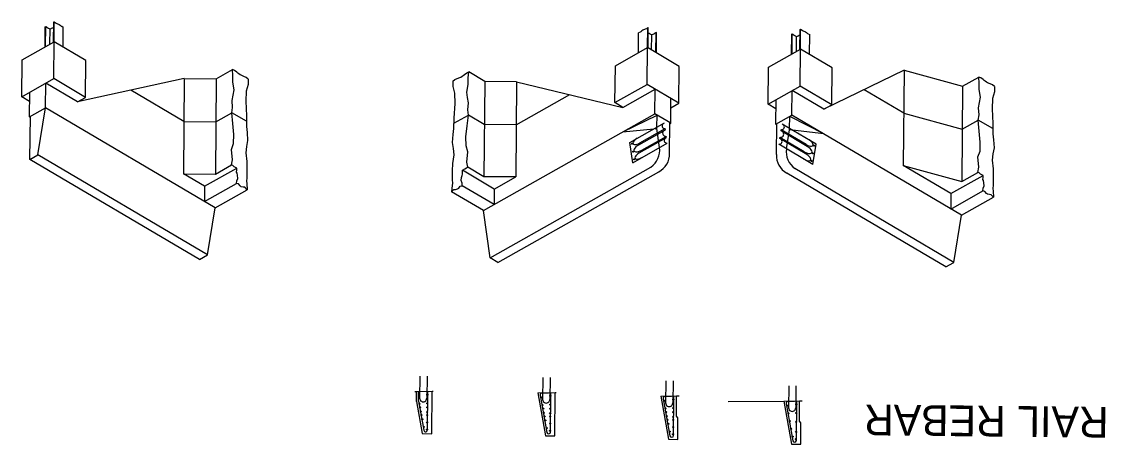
# Model space of a CAD drawing. Extents: x 631918 to 632319, y 373181 to 373282.
# Drawn here: x 631918.3 to 632006.4, y 373247.3 to 373281.7 of the extents above; entities that cross this region are included whole.
import ezdxf

# ---------------------------------------------------------------- set-up
doc = ezdxf.new("R2010")
doc.units = 0
for name, color, linetype in [('B_Boring', 7, 'Continuous'), ('BD-PROP-COSS', 7, 'Continuous'), ('BD-REMOVE', 7, 'Continuous'), ('R_Border_Scale', 7, 'Continuous'), ('R_Proposed Const Limits Cut', 7, 'Continuous'), ('R_Road Edge of Travel', 7, 'Continuous'), ('R_Shade Removal', 7, 'Continuous')]:
    doc.layers.add(name, color=color, linetype=linetype)

msp = doc.modelspace()

# ---------------------------------------------------------------- linework, layer by layer
at = {"layer": 'B_Boring'}
for p, q in [((631969.792, 373272.95), (631969.934, 373272.964)), ((631969.934, 373272.964), (631969.935, 373273.03)), ((631970.151, 373271.419), (631969.934, 373272.964)), ((631980.469, 373271.316), (631980.716, 373272.857)), ((631980.716, 373272.857), (631980.717, 373272.922)), ((631980.858, 373272.84), (631980.716, 373272.857))]:
    msp.add_line(p, q, dxfattribs=at)
at = {"layer": 'BD-PROP-COSS'}
for p, q in [((631950.664, 373252.836), (631950.646, 373251.044)), ((631951.247, 373252.83), (631951.229, 373251.038)), ((631960.663, 373252.736), (631960.645, 373250.945)), ((631961.247, 373252.73), (631961.229, 373250.939)), ((631970.661, 373252.454), (631970.643, 373250.663)), ((631971.244, 373252.449), (631971.226, 373250.657)), ((631980.657, 373252.052), (631980.64, 373250.261)), ((631981.241, 373252.047), (631981.223, 373250.255)), ((631950.56, 373250.791), (631950.568, 373251.599)), ((631951.287, 373248.474), (631951.318, 373251.591)), ((631960.452, 373251.286), (631960.996, 373248.267)), ((631961.121, 373251.452), (631960.597, 373251.457)), ((631961.286, 373248.292), (631961.318, 373251.492)), ((631971.119, 373251.171), (631970.595, 373251.176)), ((631971.283, 373248.01), (631971.315, 373251.21)), ((631950.56, 373250.791), (631950.982, 373248.447)), ((631970.45, 373251.004), (631970.994, 373247.985)), ((631980.447, 373250.602), (631980.991, 373247.583)), ((631981.115, 373250.768), (631980.592, 373250.774)), ((631981.28, 373247.608), (631981.312, 373250.808))]:
    msp.add_line(p, q, dxfattribs=at)
for centre in [(631950.606, 373251.211), (631951.274, 373251.329), (631960.528, 373251.112), (631961.273, 373251.23), (631950.641, 373250.586), (631950.693, 373250.293), (631951.263, 373250.288), (631951.267, 373250.621), (631960.64, 373250.486), (631960.693, 373250.194), (631961.263, 373250.188), (631961.266, 373250.522), (631970.525, 373250.831), (631970.638, 373250.205), (631971.264, 373250.24), (631971.271, 373250.948), (631980.522, 373250.429), (631981.267, 373250.546), (631950.753, 373249.96), (631950.806, 373249.667), (631950.865, 373249.333), (631951.257, 373249.663), (631951.26, 373249.913), (631960.753, 373249.86), (631960.805, 373249.568), (631961.257, 373249.563), (631961.259, 373249.813), (631970.69, 373249.912), (631970.75, 373249.578), (631971.257, 373249.532), (631971.261, 373249.907), (631980.634, 373249.802), (631981.26, 373249.838), (631950.978, 373248.707), (631951.246, 373248.496), (631951.251, 373249.08), (631960.865, 373249.234), (631960.977, 373248.608), (631961.251, 373248.98), (631970.803, 373249.286), (631970.863, 373248.952), (631971.249, 373248.698), (631971.254, 373249.282), (631980.747, 373249.176), (631980.859, 373248.55), (631981.253, 373249.13), (631961.245, 373248.397), (631970.975, 373248.326), (631971.243, 373248.115), (631980.972, 373247.924), (631981.239, 373247.713), (631981.245, 373248.296)]:
    msp.add_circle(centre, 0.0417, dxfattribs=at)
for centre, radius, start, end in [((631960.596, 373251.312), 0.146, 89.43036, 190.21458), ((631970.594, 373251.03), 0.146, 89.43036, 190.21458), ((631950.938, 373251.041), 0.292, 179.43036, 359.43036), ((631960.937, 373250.942), 0.292, 179.43036, 359.43036), ((631970.935, 373250.66), 0.292, 179.43036, 359.43036), ((631980.59, 373250.628), 0.146, 89.43036, 190.21458), ((631980.931, 373250.258), 0.292, 179.43036, 359.43036), ((631961.14, 373248.293), 0.146, 190.21458, 359.43036), ((631971.138, 373248.011), 0.146, 190.21458, 359.43036), ((631981.134, 373247.609), 0.146, 190.21458, 359.43036)]:
    msp.add_arc(centre, radius, start, end, dxfattribs=at)
msp.add_ellipse((631951.134, 373248.476), major_axis=(-0.002, -0.161), ratio=0.951273, start_param=4.900609, end_param=7.853982, dxfattribs=at)
at = {"layer": 'R_Border_Scale'}
for p, q in [((631931.485, 373273.544), (631927.18, 373276.087)), ((631990.004, 373274.212), (631986.775, 373276.119)), ((631958.498, 373273.275), (631962.853, 373275.732)), ((631934.083, 373273.518), (631935.39, 373274.255)), ((631936.563, 373273.562), (631935.39, 373274.255)), ((631953.422, 373273.395), (631954.608, 373274.064)), ((631955.9, 373273.301), (631954.608, 373274.064)), ((631990.004, 373274.212), (631994.754, 373272.915)), ((631931.485, 373273.544), (631934.083, 373273.518)), ((631958.498, 373273.275), (631955.9, 373273.301)), ((631994.754, 373272.915), (631996.061, 373273.652)), ((631997.234, 373272.959), (631996.061, 373273.652)), ((631950.403, 373251.591), (631951.664, 373251.604)), ((631960.246, 373251.49), (631961.663, 373251.504)), ((631970.244, 373251.209), (631971.536, 373251.222)), ((631980.24, 373250.806), (631981.532, 373250.819))]:
    msp.add_line(p, q, dxfattribs=at)
at = {"layer": 'R_Proposed Const Limits Cut'}
for p, q in [((631967.742, 373271.841), (631970.547, 373273.424)), ((631982.886, 373271.69), (631980.112, 373273.329)), ((631968.467, 373271.649), (631970.626, 373272.867)), ((631968.499, 373270.988), (631970.714, 373272.237)), ((631968.547, 373271.794), (631970.613, 373272.96)), ((631968.715, 373271.21), (631970.701, 373272.33)), ((631970.626, 373272.867), (631970.613, 373272.96)), ((631970.714, 373272.237), (631970.701, 373272.33)), ((631979.922, 373272.146), (631979.937, 373272.238)), ((631981.9, 373271.079), (631979.937, 373272.238)), ((631980.023, 373272.773), (631980.038, 373272.866)), ((631982.156, 373271.513), (631980.023, 373272.773)), ((631982.08, 373271.66), (631980.038, 373272.866)), ((631967.974, 373270.19), (631967.742, 373271.841)), ((631967.974, 373270.19), (631970.779, 373271.773)), ((631982.621, 373270.045), (631979.848, 373271.683)), ((631982.112, 373270.852), (631979.922, 373272.146)), ((631982.621, 373270.045), (631982.886, 373271.69))]:
    msp.add_line(p, q, dxfattribs=at)
for centre, major_axis, ratio, start_param, end_param in [((631970.616, 373273.188), (0.267, -0.005), 0.854896, 2.174054, 4.712811), ((631980.038, 373273.094), (0.267, -0.001), 0.854896, 4.711967, 7.250724), ((631970.705, 373272.594), (0.309, -0.005), 0.854896, 2.174054, 4.712811), ((631979.938, 373272.503), (0.309, -0.001), 0.854896, 4.711967, 7.250724), ((631968.44, 373271.984), (-0.44, -0.248), 0.432148, 4.712389, 7.853982), ((631968.591, 373271.43), (-0.508, -0.287), 0.432148, 4.712389, 7.853982), ((631970.783, 373272.002), (0.267, -0.005), 0.854896, 2.174054, 4.712811), ((631979.848, 373271.911), (0.267, -0.001), 0.854896, 4.711967, 7.250724), ((631982.028, 373271.296), (0.502, -0.297), 0.432148, 4.712389, 7.853982), ((631982.191, 373271.847), (0.435, -0.257), 0.432148, 4.712389, 7.853982), ((631968.606, 373270.798), (-0.44, -0.248), 0.432148, 4.712389, 7.853982), ((631982.001, 373270.664), (0.435, -0.257), 0.432148, 4.712389, 7.853982)]:
    msp.add_ellipse(centre, major_axis=major_axis, ratio=ratio, start_param=start_param, end_param=end_param, dxfattribs=at)
for centre, major_axis in [((631967.915, 373271.727), (-0.0216, -0.0437)), ((631968.539, 373271.74), (-0.0216, -0.0437)), ((631982.086, 373271.605), (0.0207, -0.0441)), ((631982.711, 373271.58), (0.0207, -0.0441)), ((631968.003, 373271.098), (-0.0216, -0.0437)), ((631968.091, 373270.468), (-0.0216, -0.0437)), ((631968.628, 373271.11), (-0.0216, -0.0437)), ((631981.985, 373270.978), (0.0207, -0.0441)), ((631982.61, 373270.952), (0.0207, -0.0441)), ((631982.509, 373270.325), (0.0207, -0.0441))]:
    msp.add_ellipse(centre, major_axis=major_axis, ratio=0.68171, dxfattribs=at)
at = {"layer": 'R_Road Edge of Travel'}
for p, q in [((631920.205, 373279.609), (631920.221, 373281.244)), ((631920.246, 373279.632), (631920.262, 373281.267)), ((631920.598, 373279.831), (631920.61, 373281.062)), ((631920.89, 373279.996), (631920.906, 373281.631)), ((631920.931, 373280.019), (631920.947, 373281.654)), ((631921.667, 373279.595), (631921.683, 373281.219)), ((631969.179, 373279.539), (631969.195, 373281.174)), ((631969.219, 373279.515), (631969.236, 373281.15)), ((631981.602, 373279.416), (631981.618, 373281.051)), ((631968.435, 373279.13), (631968.451, 373280.754)), ((631969.508, 373279.345), (631969.52, 373280.575)), ((631969.856, 373279.139), (631969.872, 373280.774)), ((631969.897, 373279.115), (631969.913, 373280.75)), ((631980.876, 373279.006), (631980.892, 373280.641)), ((631980.917, 373279.029), (631980.933, 373280.664)), ((631981.269, 373279.228), (631981.281, 373280.459)), ((631981.561, 373279.392), (631981.577, 373281.028)), ((631982.338, 373278.992), (631982.354, 373280.616))]:
    msp.add_line(p, q, dxfattribs=at)
for points in [[(631920.221, 373281.244), (631920.262, 373281.267), (631920.308, 373281.242), (631920.346, 373281.206), (631920.421, 373281.15), (631920.457, 373281.136), (631920.537, 373281.104), (631920.61, 373281.062), (631920.691, 373281.09), (631920.736, 373281.115), (631920.839, 373281.166), (631920.868, 373281.17), (631920.902, 373281.19)], [(631920.906, 373281.631), (631920.947, 373281.654), (631921.059, 373281.562), (631921.148, 373281.517), (631921.348, 373281.429), (631921.423, 373281.37), (631921.48, 373281.32), (631921.511, 373281.296), (631921.566, 373281.275), (631921.683, 373281.219)], [(631969.236, 373281.15), (631969.195, 373281.174), (631969.081, 373281.085), (631968.992, 373281.041), (631968.79, 373280.957), (631968.714, 373280.9), (631968.656, 373280.851), (631968.624, 373280.828), (631968.569, 373280.808), (631968.451, 373280.754)], [(631981.577, 373281.028), (631981.618, 373281.051), (631981.73, 373280.959), (631981.819, 373280.914), (631982.019, 373280.825), (631982.094, 373280.767), (631982.151, 373280.717), (631982.182, 373280.693), (631982.237, 373280.672), (631982.354, 373280.616)], [(631969.913, 373280.75), (631969.872, 373280.774), (631969.827, 373280.749), (631969.787, 373280.714), (631969.711, 373280.659), (631969.675, 373280.646), (631969.594, 373280.616), (631969.52, 373280.575), (631969.44, 373280.605), (631969.396, 373280.631), (631969.293, 373280.685), (631969.265, 373280.689), (631969.231, 373280.709)], [(631980.892, 373280.641), (631980.933, 373280.664), (631980.978, 373280.638), (631981.017, 373280.602), (631981.092, 373280.546), (631981.128, 373280.533), (631981.208, 373280.5), (631981.281, 373280.459), (631981.362, 373280.487), (631981.407, 373280.512), (631981.51, 373280.563), (631981.539, 373280.567), (631981.573, 373280.586)]]:
    msp.add_lwpolyline(points, dxfattribs=at)
at = {"layer": 'R_Shade Removal'}
for p, q in [((631918.328, 373278.55), (631920.941, 373280.024)), ((631920.911, 373277.024), (631920.941, 373280.024)), ((631923.524, 373278.498), (631920.941, 373280.024)), ((631966.557, 373278.071), (631969.169, 373279.545)), ((631969.14, 373276.545), (631969.169, 373279.545)), ((631971.753, 373278.019), (631969.169, 373279.545)), ((631978.999, 373277.947), (631981.612, 373279.421)), ((631981.582, 373276.421), (631981.612, 373279.421)), ((631984.195, 373277.895), (631981.612, 373279.421)), ((631918.298, 373275.55), (631918.328, 373278.55)), ((631923.494, 373275.499), (631923.524, 373278.498)), ((631934.118, 373277.018), (631935.425, 373277.755)), ((631955.935, 373276.801), (631954.643, 373277.564)), ((631966.527, 373275.071), (631966.557, 373278.071)), ((631971.723, 373275.019), (631971.753, 373278.019)), ((631978.969, 373274.947), (631978.999, 373277.947)), ((631990.039, 373277.712), (631983.511, 373274.527)), ((631984.165, 373274.895), (631984.195, 373277.895)), ((631990.039, 373277.712), (631989.962, 373269.963)), ((631990.039, 373277.712), (631994.789, 373276.415)), ((631918.298, 373275.55), (631920.911, 373277.024)), ((631920.238, 373274.656), (631920.258, 373276.656)), ((631922.841, 373275.13), (631920.258, 373276.656)), ((631923.494, 373275.499), (631920.911, 373277.024)), ((631931.52, 373277.044), (631922.841, 373275.13)), ((631931.52, 373277.044), (631931.443, 373269.294)), ((631931.52, 373277.044), (631934.118, 373277.018)), ((631934.118, 373277.018), (631934.041, 373269.268)), ((631955.935, 373276.801), (631955.858, 373269.052)), ((631958.533, 373276.775), (631955.935, 373276.801)), ((631958.533, 373276.775), (631958.456, 373269.026)), ((631958.533, 373276.775), (631967.173, 373274.689)), ((631994.789, 373276.415), (631996.096, 373277.152)), ((631918.931, 373273.919), (631918.951, 373275.919)), ((631966.527, 373275.071), (631969.14, 373276.545)), ((631967.173, 373274.689), (631969.785, 373276.163)), ((631971.723, 373275.019), (631969.14, 373276.545)), ((631969.766, 373274.164), (631969.785, 373276.163)), ((631978.969, 373274.947), (631981.582, 373276.421)), ((631980.909, 373274.053), (631980.928, 373276.053)), ((631983.511, 373274.527), (631980.928, 373276.053)), ((631984.165, 373274.895), (631981.582, 373276.421)), ((631994.789, 373276.415), (631994.712, 373268.665)), ((631918.944, 373275.169), (631918.298, 373275.55)), ((631922.841, 373275.13), (631923.494, 373275.499)), ((631967.173, 373274.689), (631966.527, 373275.071)), ((631971.057, 373273.401), (631971.077, 373275.401)), ((631971.069, 373274.651), (631971.723, 373275.019)), ((631979.615, 373274.566), (631978.969, 373274.947)), ((631979.602, 373273.316), (631979.622, 373275.316)), ((631983.511, 373274.527), (631984.165, 373274.895)), ((631918.931, 373273.919), (631920.238, 373274.656)), ((631919.622, 373270.829), (631920.238, 373274.656)), ((631934.014, 373266.519), (631920.238, 373274.656)), ((631955.83, 373266.302), (631969.766, 373274.164)), ((631967.153, 373272.689), (631969.945, 373274.058)), ((631971.057, 373273.401), (631969.766, 373274.164)), ((631969.935, 373273.078), (631969.945, 373274.058)), ((631979.602, 373273.316), (631980.909, 373274.053)), ((631994.685, 373265.915), (631980.909, 373274.053)), ((631919.003, 373273.876), (631918.931, 373273.919)), ((631918.969, 373270.46), (631919.004, 373273.96)), ((631970.96, 373270.943), (631970.985, 373273.443)), ((631970.984, 373273.36), (631971.057, 373273.401)), ((631979.674, 373273.273), (631979.602, 373273.316)), ((631979.65, 373270.857), (631979.675, 373273.357)), ((631980.717, 373272.971), (631980.727, 373273.95)), ((631983.492, 373272.527), (631980.727, 373273.95)), ((631967.153, 373272.689), (631969.69, 373272.94)), ((631983.492, 373272.527), (631980.96, 373272.828)), ((631918.969, 373270.46), (631919.622, 373270.829)), ((631933.398, 373262.691), (631919.622, 373270.829)), ((631932.745, 373262.323), (631918.969, 373270.46)), ((631933.165, 373268.277), (631935.778, 373269.751)), ((631934.041, 373269.268), (631935.348, 373270.005)), ((631955.858, 373269.052), (631954.566, 373269.814)), ((631956.369, 373262.463), (631969.434, 373269.833)), ((631994.069, 373262.088), (631981.154, 373269.717)), ((631993.836, 373267.674), (631989.962, 373269.963)), ((631989.962, 373269.963), (631994.712, 373268.665)), ((631933.165, 373268.277), (631931.443, 373269.294)), ((631931.443, 373269.294), (631934.041, 373269.268)), ((631956.714, 373268.043), (631954.131, 373269.569)), ((631958.456, 373269.026), (631955.858, 373269.052)), ((631956.714, 373268.043), (631958.456, 373269.026)), ((631957.015, 373262.081), (631970.08, 373269.452)), ((631993.416, 373261.719), (631980.501, 373269.348)), ((631993.836, 373267.674), (631996.449, 373269.148)), ((631994.712, 373268.665), (631996.019, 373269.402)), ((631933.153, 373267.027), (631935.766, 373268.501)), ((631933.165, 373268.277), (631933.153, 373267.027)), ((631934.014, 373266.519), (631936.627, 373267.993)), ((631956.701, 373266.793), (631954.118, 373268.319)), ((631956.714, 373268.043), (631956.701, 373266.793)), ((631993.824, 373266.424), (631996.437, 373267.898)), ((631955.83, 373266.302), (631953.247, 373267.827)), ((631993.836, 373267.674), (631993.824, 373266.424)), ((631994.685, 373265.915), (631997.298, 373267.389)), ((631933.398, 373262.691), (631934.014, 373266.519)), ((631956.369, 373262.463), (631955.83, 373266.302)), ((631994.069, 373262.088), (631994.685, 373265.915)), ((631932.745, 373262.323), (631933.398, 373262.691)), ((631957.015, 373262.081), (631956.369, 373262.463)), ((631993.416, 373261.719), (631994.069, 373262.088)), ((631950.247, 373251.59), (631950.403, 373251.591)), ((631950.395, 373250.768), (631950.403, 373251.591)), ((631951.629, 373248.159), (631951.664, 373251.604)), ((631951.664, 373251.604), (631951.747, 373251.605)), ((631960.246, 373251.49), (631960.878, 373247.984)), ((631961.628, 373247.976), (631961.663, 373251.504)), ((631961.663, 373251.504), (631961.746, 373251.505)), ((631970.244, 373251.209), (631970.876, 373247.702)), ((631971.519, 373249.571), (631971.536, 373251.222)), ((631971.536, 373251.222), (631971.744, 373251.224)), ((631950.395, 373250.768), (631950.864, 373248.167)), ((631975.739, 373250.761), (631980.24, 373250.806)), ((631980.24, 373250.806), (631980.872, 373247.3)), ((631981.516, 373249.169), (631981.532, 373250.819)), ((631981.532, 373250.819), (631981.74, 373250.821)), ((631971.643, 373249.445), (631971.519, 373249.571)), ((631971.626, 373247.695), (631971.643, 373249.445)), ((631981.64, 373249.042), (631981.516, 373249.169)), ((631981.622, 373247.293), (631981.64, 373249.042)), ((631950.864, 373248.167), (631951.629, 373248.159)), ((631960.878, 373247.984), (631961.628, 373247.976)), ((631970.876, 373247.702), (631971.626, 373247.695)), ((631980.872, 373247.3), (631981.622, 373247.293))]:
    msp.add_line(p, q, dxfattribs=at)
for points in [[(631936.627, 373267.993), (631936.442, 373268.192), (631936.306, 373268.194), (631936.146, 373268.235), (631936.051, 373268.3), (631936.051, 373268.3), (631935.933, 373268.461), (631935.933, 373268.461), (631935.766, 373268.501), (631935.784, 373268.716), (631935.873, 373268.91), (631935.873, 373268.91), (631935.836, 373269.166), (631935.806, 373269.334), (631935.759, 373269.431), (631935.784, 373269.598), (631935.778, 373269.751), (631935.579, 373269.864), (631935.46, 373269.962), (631935.46, 373269.962), (631935.348, 373270.005), (631935.438, 373270.433), (631935.362, 373271.26), (631935.529, 373271.74), (631935.55, 373272.468), (631935.461, 373273.364), (631935.39, 373274.255), (631935.447, 373274.68), (631935.4, 373275.255), (631935.498, 373275.674), (631935.558, 373276.121), (631935.467, 373276.738), (631935.459, 373277.27), (631935.425, 373277.755)], [(631936.716, 373276.992), (631936.55, 373277.125), (631936.363, 373277.203), (631936.147, 373277.297), (631936.066, 373277.333), (631935.953, 373277.41), (631935.875, 373277.471), (631935.778, 373277.548), (631935.592, 373277.683), (631935.425, 373277.755)], [(631953.247, 373267.827), (631953.436, 373268.023), (631953.572, 373268.022), (631953.732, 373268.06), (631953.829, 373268.123), (631953.829, 373268.123), (631953.95, 373268.282), (631953.95, 373268.282), (631954.118, 373268.319), (631954.105, 373268.534), (631954.019, 373268.729), (631954.019, 373268.729), (631954.061, 373268.985), (631954.095, 373269.152), (631954.144, 373269.248), (631954.121, 373269.416), (631954.131, 373269.569), (631954.332, 373269.678), (631954.453, 373269.773), (631954.453, 373269.773), (631954.566, 373269.814), (631954.484, 373270.244), (631954.576, 373271.069), (631954.419, 373271.552), (631954.413, 373272.28), (631954.519, 373273.175), (631954.608, 373274.064), (631954.559, 373274.49), (631954.618, 373275.064), (631954.528, 373275.484), (631954.477, 373275.933), (631954.581, 373276.548), (631954.599, 373277.079), (631954.643, 373277.564)], [(631953.337, 373276.827), (631953.506, 373276.956), (631953.694, 373277.03), (631953.912, 373277.121), (631953.994, 373277.155), (631954.108, 373277.23), (631954.188, 373277.289), (631954.286, 373277.364), (631954.475, 373277.495), (631954.643, 373277.564)], [(631936.716, 373276.992), (631936.71, 373276.559), (631936.542, 373276.009), (631936.52, 373275.178), (631936.561, 373273.986), (631936.565, 373273.138), (631936.62, 373272.649), (631936.666, 373271.992), (631936.568, 373271.514), (631936.507, 373271.003), (631936.598, 373270.298), (631936.604, 373269.69), (631936.611, 373268.97), (631936.566, 373268.699), (631936.566, 373268.699), (631936.589, 373268.491), (631936.627, 373267.993)], [(631953.337, 373276.827), (631953.335, 373276.393), (631953.491, 373275.841), (631953.497, 373275.009), (631953.432, 373273.819), (631953.411, 373272.971), (631953.347, 373272.483), (631953.287, 373271.827), (631953.376, 373271.347), (631953.427, 373270.835), (631953.322, 373270.132), (631953.304, 373269.524), (631953.282, 373268.805), (631953.322, 373268.532), (631953.322, 373268.532), (631953.295, 373268.325), (631953.247, 373267.827)], [(631997.298, 373267.389), (631997.113, 373267.589), (631996.977, 373267.59), (631996.817, 373267.632), (631996.722, 373267.697), (631996.722, 373267.697), (631996.604, 373267.858), (631996.604, 373267.858), (631996.437, 373267.898), (631996.454, 373268.113), (631996.544, 373268.306), (631996.544, 373268.306), (631996.507, 373268.563), (631996.477, 373268.731), (631996.43, 373268.828), (631996.455, 373268.995), (631996.449, 373269.148), (631996.25, 373269.261), (631996.131, 373269.358), (631996.131, 373269.358), (631996.019, 373269.402), (631996.109, 373269.83), (631996.033, 373270.657), (631996.2, 373271.137), (631996.221, 373271.865), (631996.132, 373272.761), (631996.061, 373273.652), (631996.118, 373274.077), (631996.071, 373274.652), (631996.169, 373275.07), (631996.229, 373275.518), (631996.138, 373276.134), (631996.13, 373276.666), (631996.096, 373277.152)], [(631997.387, 373276.389), (631997.221, 373276.522), (631997.034, 373276.599), (631996.818, 373276.694), (631996.737, 373276.73), (631996.624, 373276.807), (631996.545, 373276.868), (631996.448, 373276.945), (631996.262, 373277.08), (631996.096, 373277.152)], [(631997.387, 373276.389), (631997.381, 373275.955), (631997.213, 373275.406), (631997.191, 373274.575), (631997.232, 373273.383), (631997.236, 373272.535), (631997.291, 373272.046), (631997.337, 373271.389), (631997.239, 373270.911), (631997.178, 373270.4), (631997.268, 373269.695), (631997.275, 373269.087), (631997.282, 373268.367), (631997.237, 373268.096), (631997.237, 373268.096), (631997.259, 373267.887), (631997.298, 373267.389)]]:
    msp.add_lwpolyline(points, dxfattribs=at)
for centre, radius, start, end in [((631968.54, 373271.193), 1.627, 303.33523, 7.98399), ((631969.342, 373270.894), 1.62, 297.10598, 1.75474), ((631981.267, 373270.775), 1.62, 177.10598, 241.75474), ((631982.075, 373271.058), 1.627, 170.87673, 235.52548)]:
    msp.add_arc(centre, radius, start, end, dxfattribs=at)

# ---------------------------------------------------------------- texts
at = {"layer": 'BD-REMOVE'}
msp.add_text('RAIL REBAR', height=2.5, rotation=179.43036, dxfattribs=at).set_placement((632006.661, 373250.332))

doc.saveas('drawing.dxf')
